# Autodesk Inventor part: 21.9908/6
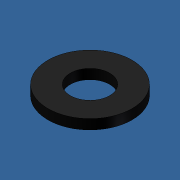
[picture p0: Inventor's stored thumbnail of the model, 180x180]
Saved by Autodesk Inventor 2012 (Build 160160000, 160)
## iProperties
Created: 2016-08
Part Number: 21.9908/6
Material: Default
Document SubType Name: Modeling
Designer: Admin
Density: 1 g/cm^3
Description: M8 Nylon Washer Black
Mass: 0.418008 g
Surface Area: 5.72273 cm^2
Volume: 0.418008 cm^3
Author: Admin
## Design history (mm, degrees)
sketch "Sketch1"
  geometry: C1 r 4.2 at (0, 0); C2 r 9 at (0, 0); 1 further point
  constraints: 2 centre point, 2 coincident
  dimensions: "d0" = 8.4 diameter of C1; "d1" = 18 diameter of C2
extrude "Extrusion1" new body sketch "Sketch1" distance "d2" = 2.1; taper "d3" = 0 deg
body "Solid1"
